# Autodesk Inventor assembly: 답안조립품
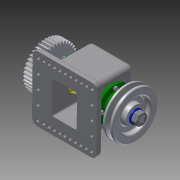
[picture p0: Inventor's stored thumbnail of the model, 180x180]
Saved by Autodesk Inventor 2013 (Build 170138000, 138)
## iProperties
Created: 2018-11
Part Number: 답안조립품
Document SubType Name: Assembly
Designer: Administrator
Author: Administrator
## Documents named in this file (13)
- C:\Users\Administrator\Desktop\481107V1017\답안조립품.iam
- C:\Users\Administrator\Desktop\481107V1017\본체.ipt
- C:\Users\Administrator\Desktop\481107V1017\커버.ipt
- C:\Users\Administrator\Desktop\481107V1017\베어링 6203.ipt
- C:\Users\Administrator\Desktop\481107V1017\축.ipt
- C:\Users\Administrator\Desktop\481107V1017\오일 실 26 38 8.ipt
- C:\Users\Administrator\Desktop\481107V1017\볼트 M4.ipt
- C:\Users\Administrator\Desktop\481107V1017\키 5x5x12.ipt
- C:\Users\Administrator\Desktop\481107V1017\부시.ipt
- C:\Users\Administrator\Desktop\481107V1017\V벨트풀리.ipt
- C:\Users\Administrator\Desktop\481107V1017\스퍼기어.ipt
- C:\Users\Administrator\Desktop\481107V1017\와셔 12x24.ipt
- C:\Users\Administrator\Desktop\481107V1017\너트 M12x1.25.ipt
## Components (1 placed, 1 different names)
1. V벨트풀리:1
